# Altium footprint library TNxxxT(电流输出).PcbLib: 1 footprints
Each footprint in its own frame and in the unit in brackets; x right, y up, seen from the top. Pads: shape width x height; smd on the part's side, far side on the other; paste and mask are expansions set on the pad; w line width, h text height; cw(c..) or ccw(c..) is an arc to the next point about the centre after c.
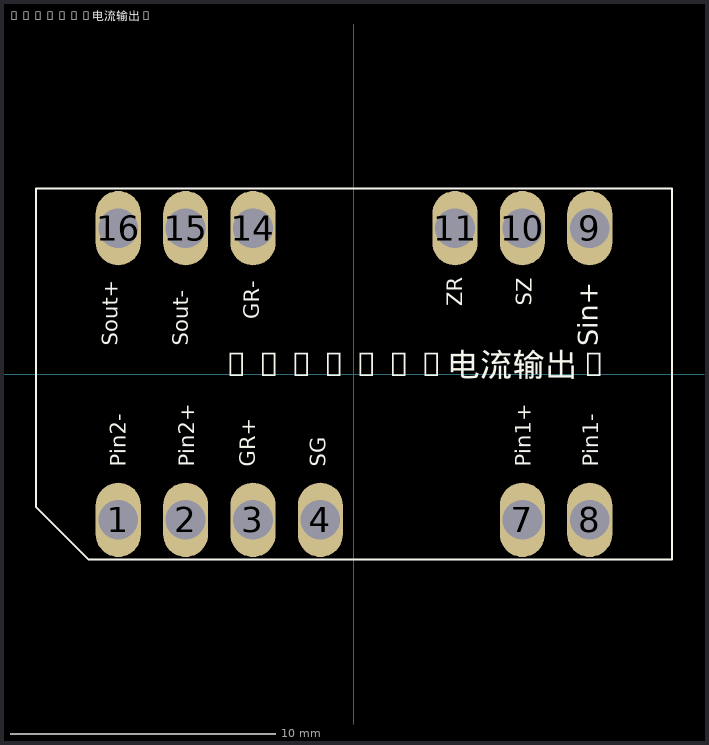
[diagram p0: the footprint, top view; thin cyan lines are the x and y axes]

## TNxxxT(电流输出) [mm]
pads (12):
  oval 1.7x2.8 hole 1.5 mask+0.102: 1(-8.89,-5.5) 2(-6.35,-5.5) 3(-3.81,-5.5) 4(-1.27,-5.5) 7(6.35,-5.5) 8(8.89,-5.5) 9(8.89,5.5) 10(6.35,5.5) 11(3.81,5.5) 14(-3.81,5.5) 15(-6.35,5.5) 16(-8.89,5.5)
Top Overlay:
  lines w0.076: -12,-5.003 -12,7 12,7 12,-7 -10.003,-7 -12,-5.003
  text "Pin1-" at 9.418,-3.494 h1
  text "Pin1+" at 6.878,-3.494 h1
  text "SG" at -0.85,-3.494 h1
  text "GR+" at -3.514,-3.494 h1
  text "Pin2+" at -5.822,-3.494 h1
  text "Pin2-" at -8.405,-3.494 h1
  text "TNxxxT(电流输出)" at -5.037,-0.393 h1.52
  text "Sin+" at 9.432,1.043 h1.27
  text "SZ" at 6.914,2.577 h1
  text "ZR" at 4.299,2.562 h1
  text "GR-" at -3.368,2.066 h1
  text "Sout-" at -6.048,1.068 h1
  text "Sout+" at -8.712,1.064 h1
